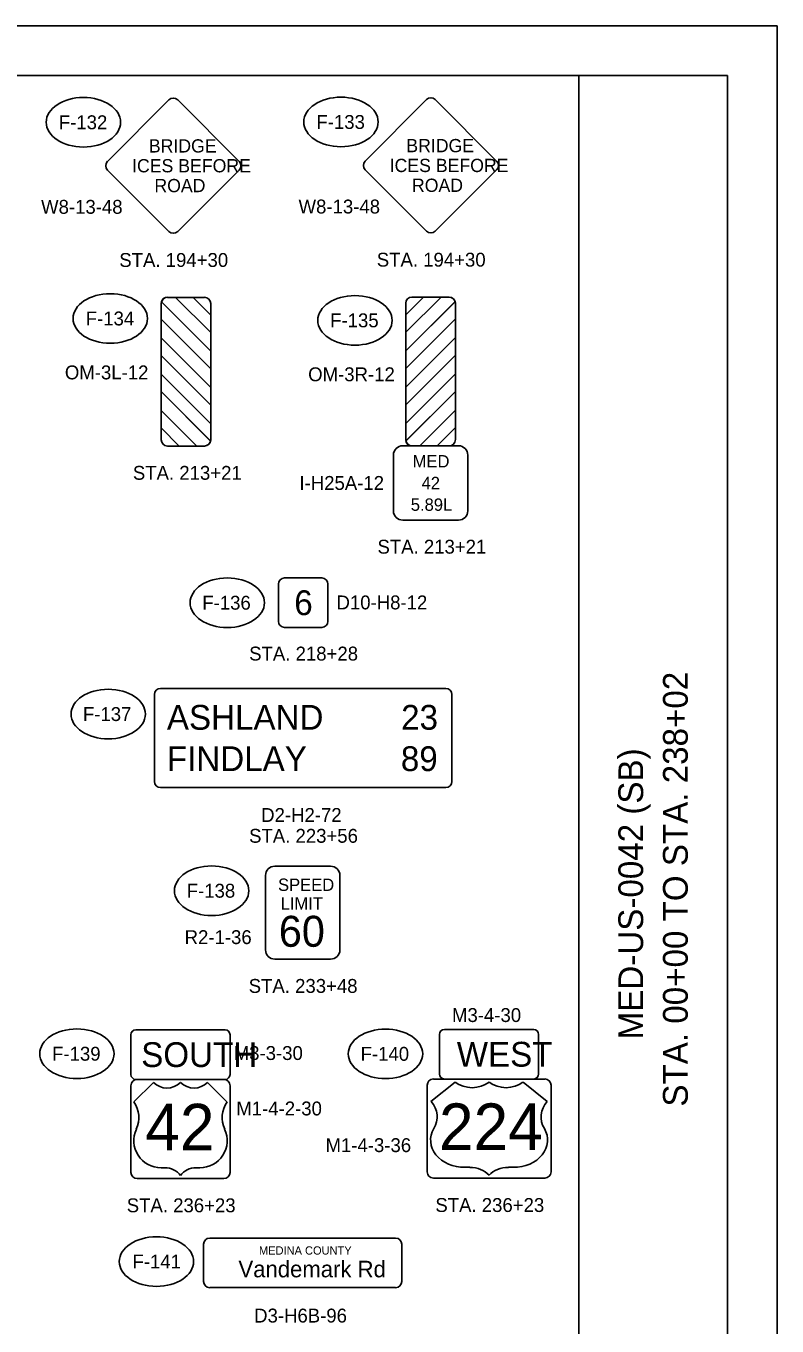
# Model space of a CAD drawing. Extents: x 0 to 34, y 0 to 22.
# Drawn here: x 26.42 to 34, y 8.89 to 22 of the extents above; entities that cross this region are included whole.
import ezdxf

# ---------------------------------------------------------------- set-up
doc = ezdxf.new("R2010")
doc.units = 0
for name, color, linetype in [('SH_Border', 7, 'Continuous'), ('SH_Cut_Line', 7, 'Continuous'), ('SH_Data', 7, 'Continuous'), ('SH_Text', 7, 'Continuous'), ('SN_P_Signs', 7, 'Continuous')]:
    doc.layers.add(name, color=color, linetype=linetype)

msp = doc.modelspace()

# ---------------------------------------------------------------- linework, layer by layer
at = {"layer": 'SH_Border'}
msp.add_line((32, 0.5), (32, 21.5), dxfattribs=at)
msp.add_lwpolyline([(1.5, 21.5), (33.5, 21.5), (33.5, 0.5), (1.5, 0.5)], close=True, dxfattribs=at)
at = {"layer": 'SH_Cut_Line'}
msp.add_lwpolyline([(0, 0), (34, 0), (34, 22), (0, 22)], close=True, dxfattribs=at)
at = {"layer": 'SH_Text'}
for centre in [(27.004, 21.029), (29.602, 21.032), (27.275, 19.05), (29.743, 19.031), (28.455, 16.183), (27.254, 15.06), (28.297, 13.278), (26.938, 11.634), (30.051, 11.633), (27.741, 9.538)]:
    msp.add_ellipse(centre, major_axis=(0.375, 0), ratio=0.666667, dxfattribs=at)
at = {"layer": 'SN_P_Signs'}
for p, q in [((28.288, 18.72), (27.788, 19.22)), ((28.288, 18.908), (27.933, 19.263)), ((28.288, 19.085), (28.11, 19.263)), ((30.256, 18.911), (30.611, 19.266)), ((30.256, 19.087), (30.434, 19.266)), ((30.256, 18.722), (30.756, 19.222)), ((28.288, 18.543), (27.788, 19.043)), ((30.256, 18.545), (30.756, 19.045)), ((28.288, 18.354), (27.788, 18.854)), ((30.256, 18.357), (30.756, 18.857)), ((28.288, 18.177), (27.788, 18.677)), ((30.256, 18.18), (30.756, 18.68)), ((28.288, 17.989), (27.788, 18.489)), ((30.256, 17.991), (30.756, 18.491)), ((28.288, 17.812), (27.788, 18.312)), ((30.256, 17.814), (30.756, 18.314)), ((28.148, 17.763), (27.788, 18.123)), ((30.396, 17.766), (30.756, 18.126)), ((27.971, 17.763), (27.788, 17.947)), ((30.573, 17.766), (30.756, 17.949)), ((27.483, 11.425), (27.483, 11.825)), ((27.533, 11.875), (28.433, 11.875)), ((28.483, 11.825), (28.483, 11.425)), ((30.596, 11.429), (30.596, 11.829)), ((30.646, 11.879), (31.546, 11.879)), ((31.596, 11.829), (31.596, 11.429)), ((27.71, 11.343), (27.514, 11.148)), ((28.433, 11.375), (27.533, 11.375)), ((28.452, 11.148), (28.256, 11.343)), ((30.754, 11.348), (30.51, 11.153)), ((31.546, 11.379), (30.646, 11.379)), ((31.682, 11.153), (31.438, 11.348)), ((27.788, 10.484), (27.827, 10.484)), ((28.139, 10.484), (28.178, 10.484)), ((30.852, 10.489), (30.901, 10.489)), ((31.291, 10.489), (31.34, 10.489))]:
    msp.add_line(p, q, dxfattribs=at)
for points in [[(27.867, 21.254), (27.248, 20.635)], [(28.574, 20.635), (27.955, 21.254)], [(30.465, 21.257), (29.846, 20.638)], [(31.172, 20.638), (30.553, 21.257)], [(27.248, 20.547), (27.867, 19.928)], [(27.955, 19.928), (28.574, 20.547)], [(29.846, 20.55), (30.465, 19.931)], [(30.553, 19.931), (31.172, 20.55)], [(27.788, 17.826), (27.788, 19.201)], [(27.851, 19.263), (27.933, 19.263), (28.288, 18.908), (28.288, 18.72), (27.791, 19.217)], [(27.851, 19.263), (28.226, 19.263)], [(28.11, 19.263), (28.226, 19.263)], [(28.288, 19.201), (28.288, 19.085), (28.11, 19.263)], [(28.288, 19.201), (28.288, 17.826)], [(30.256, 19.203), (30.256, 19.087), (30.434, 19.266)], [(30.693, 19.266), (30.611, 19.266), (30.256, 18.911), (30.256, 18.722), (30.754, 19.22)], [(30.256, 19.203), (30.256, 17.828)], [(30.693, 19.266), (30.318, 19.266)], [(30.434, 19.266), (30.318, 19.266)], [(30.756, 17.828), (30.756, 19.203)], [(27.788, 18.854), (27.788, 19.043), (28.288, 18.543), (28.288, 18.354), (27.788, 18.854)], [(30.756, 18.857), (30.756, 19.045), (30.256, 18.545), (30.256, 18.357), (30.756, 18.857)], [(27.788, 18.489), (27.788, 18.677), (28.288, 18.177), (28.288, 17.989), (27.788, 18.489)], [(30.756, 18.491), (30.756, 18.68), (30.256, 18.18), (30.256, 17.991), (30.756, 18.491)], [(28.226, 17.763), (28.148, 17.763), (27.788, 18.123), (27.788, 18.312), (28.287, 17.813)], [(30.318, 17.766), (30.396, 17.766), (30.756, 18.126), (30.756, 18.314), (30.257, 17.816)], [(27.788, 17.826), (27.788, 17.947), (27.971, 17.763)], [(30.756, 17.828), (30.756, 17.949), (30.573, 17.766)], [(28.226, 17.763), (27.851, 17.763)], [(27.971, 17.763), (27.851, 17.763)], [(30.787, 17.766), (30.225, 17.766)], [(30.318, 17.766), (30.693, 17.766)], [(30.573, 17.766), (30.693, 17.766)], [(30.131, 17.672), (30.131, 17.11)], [(30.881, 17.11), (30.881, 17.672)], [(30.225, 17.016), (30.787, 17.016)], [(29.408, 16.433), (29.033, 16.433)], [(28.971, 16.371), (28.971, 15.996)], [(29.471, 15.996), (29.471, 16.371)], [(29.033, 15.933), (29.408, 15.933)], [(27.721, 15.256), (27.721, 14.381)], [(30.658, 15.318), (27.783, 15.318)], [(30.721, 14.381), (30.721, 15.256)], [(27.783, 14.318), (30.658, 14.318)], [(29.497, 13.526), (28.935, 13.526)], [(28.841, 13.432), (28.841, 12.682)], [(29.591, 12.682), (29.591, 13.432)], [(28.935, 12.588), (29.497, 12.588)], [(27.483, 11.312), (27.483, 10.437)], [(28.421, 11.375), (27.546, 11.375)], [(28.483, 10.437), (28.483, 11.312)], [(30.471, 11.317), (30.471, 10.442)], [(31.659, 11.379), (30.534, 11.379)], [(31.721, 10.442), (31.721, 11.317)], [(27.546, 10.375), (28.421, 10.375)], [(30.534, 10.379), (31.659, 10.379)], [(28.215, 9.712), (28.215, 9.337)], [(30.153, 9.775), (28.278, 9.775)], [(30.215, 9.337), (30.215, 9.712)], [(28.278, 9.275), (30.153, 9.275)]]:
    msp.add_lwpolyline(points, dxfattribs=at)
for centre, radius, start, end in [((27.911, 21.21), 0.0625, 45, 135), ((30.509, 21.213), 0.0625, 45, 135), ((27.292, 20.591), 0.0625, 135, 225), ((28.53, 20.591), 0.0625, 315, 45), ((29.89, 20.594), 0.0625, 135, 225), ((31.128, 20.594), 0.0625, 315, 45), ((30.509, 19.975), 0.0625, 225, 315), ((27.911, 19.972), 0.0625, 225, 315), ((27.851, 19.201), 0.0625, 90, 180), ((27.851, 19.201), 0.0625, 90, 164.7237), ((28.226, 19.201), 0.0625, 0, 90), ((28.226, 19.201), 0.0625, 0, 90), ((30.318, 19.203), 0.0625, 90, 180), ((30.318, 19.203), 0.0625, 90, 180), ((30.693, 19.203), 0.0625, 0, 90), ((30.693, 19.203), 0.0625, 15.2763, 90), ((27.851, 17.826), 0.0625, 180, 270), ((27.851, 17.826), 0.0625, 180, 270), ((28.226, 17.826), 0.0625, 270, 360), ((28.226, 17.826), 0.0625, 270, 348.268), ((30.225, 17.672), 0.0938, 90, 180), ((30.318, 17.828), 0.0625, 180, 270), ((30.318, 17.828), 0.0625, 191.732, 270), ((30.693, 17.828), 0.0625, 270, 0), ((30.693, 17.828), 0.0625, 270, 0), ((30.787, 17.672), 0.0938, 0, 90), ((30.225, 17.11), 0.0938, 180, 270), ((30.787, 17.11), 0.0938, 270, 0), ((29.033, 16.371), 0.0625, 90, 180), ((29.408, 16.371), 0.0625, 0, 90), ((29.033, 15.996), 0.0625, 180, 270), ((29.408, 15.996), 0.0625, 270, 0), ((27.783, 15.256), 0.0625, 90, 180), ((30.658, 15.256), 0.0625, 0, 90), ((27.783, 14.381), 0.0625, 180, 270), ((30.658, 14.381), 0.0625, 270, 0), ((28.935, 13.432), 0.0938, 90, 180), ((29.497, 13.432), 0.0938, 0, 90), ((28.935, 12.682), 0.0938, 180, 270), ((29.497, 12.682), 0.0938, 270, 0), ((27.533, 11.825), 0.05, 90, 180), ((28.433, 11.825), 0.05, 0, 90), ((30.646, 11.829), 0.05, 90, 180), ((31.546, 11.829), 0.05, 0, 90), ((27.533, 11.425), 0.05, 180, 270), ((28.433, 11.425), 0.05, 270, 0), ((30.646, 11.429), 0.05, 180, 270), ((31.546, 11.429), 0.05, 270, 0), ((27.546, 11.312), 0.0625, 90, 180), ((27.846, 11.483), 0.195, 225.573, 314.427), ((28.12, 11.483), 0.195, 225.573, 314.427), ((28.421, 11.312), 0.0625, 0, 90), ((30.534, 11.317), 0.0625, 90, 180), ((31.659, 11.317), 0.0625, 0, 90), ((27.29, 10.991), 0.273, 334.5471, 35.0009), ((28.676, 10.991), 0.273, 144.9991, 205.4529), ((27.785, 10.757), 0.273, 154.8319, 270.6383), ((28.181, 10.757), 0.273, 269.3617, 25.1681), ((27.546, 10.437), 0.0625, 180, 270), ((27.827, 10.289), 0.195, 36.8699, 90), ((28.139, 10.289), 0.195, 90, 143.1301), ((28.421, 10.437), 0.0625, 270, 0), ((30.534, 10.442), 0.0625, 180, 270), ((31.659, 10.442), 0.0625, 270, 0), ((28.278, 9.712), 0.0625, 90, 180), ((30.153, 9.712), 0.0625, 0, 90), ((28.278, 9.337), 0.0625, 180, 270), ((30.153, 9.337), 0.0625, 270, 0)]:
    msp.add_arc(centre, radius, start, end, dxfattribs=at)
for centre, major_axis, start_param, end_param in [((30.925, 11.487), (-0.244, 0), 0.795399, 2.346194), ((31.267, 11.487), (-0.244, 0), 0.795399, 2.346194), ((30.23, 10.996), (0.342, 0), 5.838949, 6.894067), ((31.962, 10.996), (-0.342, 0), 5.672304, 6.727422), ((30.848, 10.762), (0.342, 0), 2.702327, 4.723529), ((31.344, 10.762), (-0.342, 0), 1.559657, 3.580859), ((30.901, 10.293), (-0.244, 0), 3.785094, 4.712389), ((31.291, 10.293), (-0.244, 0), 4.712389, 5.639684)]:
    msp.add_ellipse(centre, major_axis=major_axis, ratio=0.8, start_param=start_param, end_param=end_param, dxfattribs=at)

# ---------------------------------------------------------------- texts
at = {"layer": 'SH_Data'}
for s, p in [('STA. 00+00 TO STA. 238+02', (33.1, 11.101)), ('MED-US-0042 (SB)', (32.65, 11.779))]:
    msp.add_text(s, height=0.25, rotation=90, dxfattribs=at).set_placement(p)
at = {"layer": 'SH_Text'}
for s, p in [('F-132', (26.756, 20.959)), ('F-133', (29.354, 20.962)), ('W8-13-48', (26.577, 20.106)), ('W8-13-48', (29.174, 20.109)), ('STA. 194+30', (27.366, 19.57)), ('STA. 194+30', (29.963, 19.573)), ('F-134', (27.027, 18.98)), ('F-135', (29.493, 18.961)), ('OM-3L-12', (26.817, 18.436)), ('OM-3R-12', (29.271, 18.417)), ('STA. 213+21', (27.503, 17.423)), ('I-H25A-12', (29.183, 17.321)), ('STA. 213+21', (29.97, 16.678)), ('F-136', (28.203, 16.113)), ('D10-H8-12', (29.557, 16.116)), ('STA. 218+28', (28.676, 15.6)), ('F-137', (26.999, 14.99)), ('D2-H2-72', (28.797, 13.972)), ('STA. 223+56', (28.675, 13.762)), ('F-138', (28.046, 13.208)), ('R2-1-36', (28.025, 12.74)), ('STA. 233+48', (28.671, 12.248)), ('M3-4-30', (30.722, 11.954)), ('F-139', (26.688, 11.564)), ('M3-3-30', (28.52, 11.571)), ('F-140', (29.8, 11.563)), ('M1-4-2-30', (28.546, 11.012)), ('M1-4-3-36', (29.446, 10.642)), ('STA. 236+23', (27.441, 10.035)), ('STA. 236+23', (30.554, 10.038)), ('F-141', (27.499, 9.468)), ('D3-H6B-96', (28.726, 8.923))]:
    msp.add_text(s, height=0.14, dxfattribs=at).set_placement(p)
at = {"layer": 'SN_P_Signs'}
for s, height, p in [('BRIDGE', 0.1333, (27.664, 20.724)), ('BRIDGE', 0.1333, (30.261, 20.727)), ('ICES BEFORE', 0.13333, (27.495, 20.524)), ('ICES BEFORE', 0.13333, (30.093, 20.527)), ('ROAD', 0.1333, (27.72, 20.324)), ('ROAD', 0.1333, (30.318, 20.327)), ('MED', 0.125, (30.325, 17.547)), ('42', 0.125, (30.415, 17.328)), ('5.89L', 0.125, (30.306, 17.11)), ('6', 0.25, (29.131, 16.058)), ('ASHLAND', 0.25, (27.846, 14.902)), ('23', 0.25, (30.209, 14.902)), ('FINDLAY', 0.25, (27.846, 14.485)), ('89', 0.25, (30.206, 14.485)), ('SPEED', 0.125, (28.967, 13.276)), ('LIMIT', 0.125, (28.993, 13.088)), ('60', 0.3125, (28.975, 12.713)), ('SOUTH', 0.25, (27.587, 11.5)), ('WEST', 0.25, (30.77, 11.504)), ('42', 0.4688, (27.629, 10.66)), ('224', 0.4688, (30.591, 10.664)), ('MEDINA COUNTY', 0.08333, (28.775, 9.608)), ('Vandemark Rd', 0.16667, (28.568, 9.379))]:
    msp.add_text(s, height=height, dxfattribs=at).set_placement(p)

doc.saveas('drawing.dxf')
